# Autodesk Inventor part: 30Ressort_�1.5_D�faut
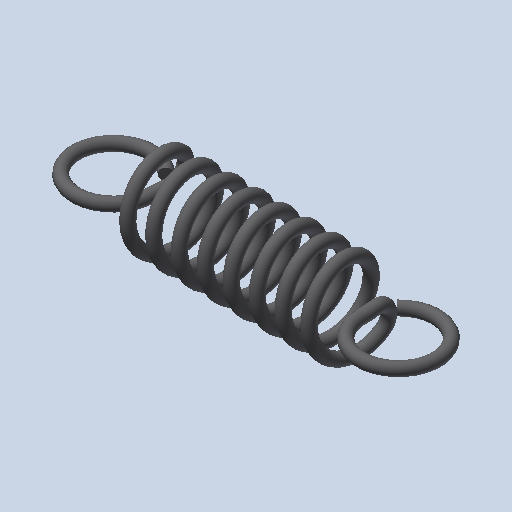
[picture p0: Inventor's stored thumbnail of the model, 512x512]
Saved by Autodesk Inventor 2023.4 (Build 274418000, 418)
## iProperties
Created: 2011-01
Part Number: 30Ressort_�1.5_D�faut
Document SubType Name: Modeling
Designer: eric
Density: 1 g/cm^3
Mass: 0.414767 g
Surface Area: 11.9129 cm^2
Volume: 0.414767 cm^3
Material: Générique
Appearance: Red
Author: eric
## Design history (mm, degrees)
feature "Base1"
node "Corps solides"
node "Corps surfaciques"
node "Solide1"
